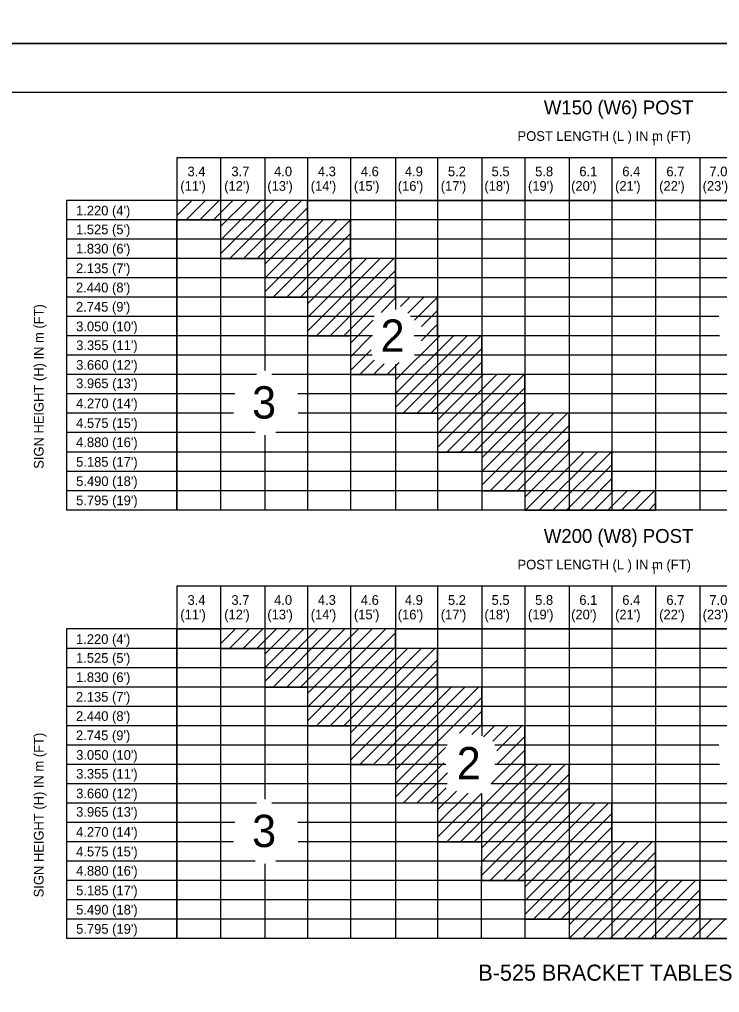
# Model space of a CAD drawing. Extents: x 637580 to 641008, y 294594 to 295782.
# Drawn here: x 639497.1 to 639714, y 294893.4 to 295195.1 of the extents above; entities that cross this region are included whole.
import ezdxf

# ---------------------------------------------------------------- set-up
doc = ezdxf.new("R2010")
doc.units = 0
for name, color, linetype in [('1', 7, 'Continuous'), ('2', 7, 'Continuous'), ('PLT-BNDY', 7, 'Continuous')]:
    doc.layers.add(name, color=color, linetype=linetype)

msp = doc.modelspace()

# ---------------------------------------------------------------- linework, layer by layer
at = {"layer": '1'}
msp.add_line((639302.31, 295172.63), (640088.31, 295172.63), dxfattribs=at)
at = {"layer": '2'}
for p, q in [((639866.29, 295152.27), (639545.88, 295152.27)), ((639545.88, 295152.27), (639545.88, 295043.01)), ((639559.39, 295152.27), (639559.39, 295043.01)), ((639573.15, 295152.27), (639573.15, 295086.26)), ((639586.4, 295152.27), (639586.4, 295043.01)), ((639599.66, 295152.27), (639599.66, 295043.01)), ((639613.67, 295152.27), (639613.67, 295105.22)), ((639626.67, 295152.27), (639626.67, 295043.01)), ((639640.43, 295152.27), (639640.43, 295043.01)), ((639653.69, 295152.27), (639653.69, 295043.01)), ((639667.45, 295152.27), (639667.45, 295043.01)), ((639680.7, 295152.27), (639680.7, 295043.01)), ((639694.21, 295152.27), (639694.21, 295043.01)), ((639707.97, 295152.27), (639707.97, 295043.01)), ((639866.29, 295139.01), (639511.65, 295139.01)), ((639511.65, 295139.01), (639511.65, 295043.01)), ((639545.88, 295139.01), (639545.88, 295133.01)), ((639551.38, 295139.01), (639545.88, 295139.01)), ((639545.88, 295138.6), (639546.29, 295139.01)), ((639545.88, 295134.36), (639550.53, 295139.01)), ((639548.78, 295133.01), (639554.78, 295139.01)), ((639586.4, 295139.01), (639551.38, 295139.01)), ((639553.02, 295133.01), (639559.02, 295139.01)), ((639557.26, 295133.01), (639563.26, 295139.01)), ((639559.39, 295130.9), (639567.5, 295139.01)), ((639559.39, 295126.65), (639571.75, 295139.01)), ((639559.39, 295122.41), (639575.99, 295139.01)), ((639562.23, 295121.01), (639580.23, 295139.01)), ((639566.47, 295121.01), (639584.47, 295139.01)), ((639586.4, 295133.01), (639586.4, 295139.01)), ((639586.4, 295139.01), (639827.27, 295139.01)), ((639570.72, 295121.01), (639586.4, 295136.7)), ((639827.27, 295133.01), (639511.65, 295133.01)), ((639545.88, 295043.01), (639545.88, 295133.01)), ((639545.88, 295133.01), (639559.39, 295133.01)), ((639545.88, 295133.01), (639559.39, 295133.01)), ((639559.39, 295133.01), (639559.39, 295121.01)), ((639559.39, 295133.01), (639559.39, 295121.01)), ((639573.15, 295119.2), (639586.96, 295133.01)), ((639573.15, 295114.95), (639591.2, 295133.01)), ((639573.15, 295110.71), (639595.44, 295133.01)), ((639575.69, 295109.01), (639599.66, 295132.98)), ((639599.66, 295133.01), (639586.4, 295133.01)), ((639599.66, 295121.01), (639599.66, 295133.01)), ((639840.28, 295127.01), (639511.65, 295127.01)), ((639579.93, 295109.01), (639599.66, 295128.74)), ((639584.17, 295109.01), (639599.66, 295124.5)), ((639840.28, 295121.01), (639511.65, 295121.01)), ((639559.39, 295121.01), (639573.15, 295121.01)), ((639559.39, 295121.01), (639573.15, 295121.01)), ((639573.15, 295121.01), (639573.15, 295109.01)), ((639573.15, 295121.01), (639573.15, 295109.01)), ((639586.4, 295107), (639600.41, 295121.01)), ((639586.4, 295102.75), (639604.66, 295121.01)), ((639586.4, 295098.51), (639608.9, 295121.01)), ((639589.14, 295097.01), (639613.14, 295121.01)), ((639613.67, 295121.01), (639599.66, 295121.01)), ((639613.67, 295109.01), (639613.67, 295121.01)), ((639593.39, 295097.01), (639613.67, 295117.29)), ((639853.28, 295115.01), (639511.65, 295115.01)), ((639597.63, 295097.01), (639613.67, 295113.05)), ((639853.28, 295109.01), (639511.65, 295109.01)), ((639573.15, 295109.01), (639586.4, 295109.01)), ((639573.15, 295109.01), (639586.4, 295109.01)), ((639586.4, 295109.01), (639586.4, 295097.01)), ((639586.4, 295109.01), (639586.4, 295097.01)), ((639609.14, 295104.28), (639613.87, 295109.01)), ((639626.67, 295109.01), (639613.67, 295109.01)), ((639615.2, 295106.09), (639618.11, 295109.01)), ((639617.45, 295104.1), (639622.36, 295109.01)), ((639619.51, 295101.92), (639626.6, 295109.01)), ((639626.67, 295097.01), (639626.67, 295109.01)), ((639607.01, 295103.01), (639511.65, 295103.01)), ((639713.86, 295103.01), (639618.23, 295103.01)), ((639621.73, 295099.9), (639626.67, 295104.84)), ((639599.66, 295094.8), (639606.72, 295101.86)), ((639621.58, 295095.51), (639626.67, 295100.6)), ((639606.46, 295097.01), (639511.65, 295097.01)), ((639586.4, 295097.01), (639599.66, 295097.01)), ((639586.4, 295097.01), (639599.66, 295097.01)), ((639599.66, 295097.01), (639599.66, 295085.01)), ((639599.66, 295097.01), (639599.66, 295085.01)), ((639599.66, 295090.56), (639606.11, 295097.01)), ((639613.67, 295083.35), (639627.33, 295097.01)), ((639613.67, 295079.11), (639631.57, 295097.01)), ((639613.67, 295074.86), (639635.81, 295097.01)), ((639616.05, 295073.01), (639640.05, 295097.01)), ((639714.04, 295097.01), (639619.44, 295097.01)), ((639640.43, 295097.01), (639626.67, 295097.01)), ((639640.43, 295085.01), (639640.43, 295097.01)), ((639620.3, 295073.01), (639640.43, 295093.14)), ((639606.35, 295091.01), (639511.65, 295091.01)), ((639599.66, 295086.31), (639606.09, 295092.74)), ((639866.29, 295091.01), (639619.55, 295091.01)), ((639602.6, 295085.01), (639607.03, 295089.44)), ((639606.84, 295085.01), (639610.13, 295088.3)), ((639611.08, 295085.01), (639614.79, 295088.71)), ((639613.67, 295088.28), (639613.67, 295043.01)), ((639624.54, 295073.01), (639640.43, 295088.9)), ((639570.59, 295085.01), (639511.65, 295085.01)), ((639866.29, 295085.01), (639575.26, 295085.01)), ((639599.66, 295085.01), (639613.67, 295085.01)), ((639599.66, 295085.01), (639613.67, 295085.01)), ((639613.67, 295085.01), (639613.67, 295073.01)), ((639613.67, 295085.01), (639613.67, 295073.01)), ((639626.67, 295070.9), (639640.78, 295085.01)), ((639626.67, 295066.66), (639645.02, 295085.01)), ((639626.67, 295062.42), (639649.27, 295085.01)), ((639629.51, 295061.01), (639653.51, 295085.01)), ((639653.69, 295085.01), (639640.43, 295085.01)), ((639653.69, 295073.01), (639653.69, 295085.01)), ((639633.75, 295061.01), (639653.69, 295080.94)), ((639563.85, 295079.01), (639511.65, 295079.01)), ((639866.29, 295079.01), (639583.36, 295079.01)), ((639638, 295061.01), (639653.69, 295076.7)), ((639563.44, 295073.01), (639511.65, 295073.01)), ((639866.29, 295073.01), (639583.5, 295073.01)), ((639613.67, 295073.01), (639626.67, 295073.01)), ((639613.67, 295073.01), (639626.67, 295073.01)), ((639626.67, 295073.01), (639626.67, 295061.01)), ((639626.67, 295073.01), (639626.67, 295061.01)), ((639640.43, 295059.2), (639654.24, 295073.01)), ((639640.43, 295054.96), (639658.48, 295073.01)), ((639640.43, 295050.72), (639662.72, 295073.01)), ((639642.97, 295049.01), (639666.97, 295073.01)), ((639667.45, 295073.01), (639653.69, 295073.01)), ((639667.45, 295061.01), (639667.45, 295073.01)), ((639647.21, 295049.01), (639667.45, 295069.25)), ((639570.17, 295067.01), (639511.65, 295067.01)), ((639573.15, 295066.19), (639573.15, 295043.01)), ((639866.29, 295067.01), (639576.49, 295067.01)), ((639651.45, 295049.01), (639667.45, 295065)), ((639866.29, 295061.01), (639511.65, 295061.01)), ((639626.67, 295061.01), (639640.43, 295061.01)), ((639626.67, 295061.01), (639640.43, 295061.01)), ((639640.43, 295061.01), (639640.43, 295049.01)), ((639640.43, 295061.01), (639640.43, 295049.01)), ((639653.69, 295047), (639667.69, 295061.01)), ((639653.94, 295043.01), (639671.94, 295061.01)), ((639658.18, 295043.01), (639676.18, 295061.01)), ((639662.42, 295043.01), (639680.42, 295061.01)), ((639680.7, 295061.01), (639667.45, 295061.01)), ((639680.7, 295049.01), (639680.7, 295061.01)), ((639666.66, 295043.01), (639680.7, 295057.05)), ((639866.29, 295055.01), (639511.65, 295055.01)), ((639670.91, 295043.01), (639680.7, 295052.8)), ((639866.29, 295049.01), (639511.65, 295049.01)), ((639640.43, 295049.01), (639653.69, 295049.01)), ((639640.43, 295049.01), (639653.69, 295049.01)), ((639653.69, 295049.01), (639653.69, 295043.01)), ((639653.69, 295049.01), (639653.69, 295043.01)), ((639675.15, 295043.01), (639681.15, 295049.01)), ((639679.39, 295043.01), (639685.39, 295049.01)), ((639694.21, 295049.01), (639680.7, 295049.01)), ((639683.64, 295043.01), (639689.64, 295049.01)), ((639687.88, 295043.01), (639693.88, 295049.01)), ((639694.21, 295043.01), (639694.21, 295049.01)), ((639692.12, 295043.01), (639694.21, 295045.1)), ((639866.29, 295043.01), (639511.65, 295043.01)), ((639653.69, 295043.01), (639545.88, 295043.01)), ((639653.69, 295043.01), (639694.21, 295043.01)), ((639866.29, 295043.01), (639694.21, 295043.01)), ((639866.29, 295019.39), (639545.88, 295019.39)), ((639545.88, 295019.39), (639545.88, 294910.13)), ((639559.39, 295019.39), (639559.39, 294910.13)), ((639573.15, 295019.39), (639573.15, 294953.39)), ((639586.4, 295019.39), (639586.4, 294910.13)), ((639599.66, 295019.39), (639599.66, 294910.13)), ((639613.67, 295019.39), (639613.67, 294910.13)), ((639626.67, 295019.39), (639626.67, 294910.13)), ((639640.43, 295019.39), (639640.33, 294973.02)), ((639653.69, 295019.39), (639653.69, 294910.13)), ((639667.45, 295019.39), (639667.45, 294910.13)), ((639680.7, 295019.39), (639680.7, 294910.13)), ((639694.21, 295019.39), (639694.21, 294910.13)), ((639707.97, 295019.39), (639707.97, 294910.13)), ((639866.29, 295006.13), (639511.65, 295006.13)), ((639511.65, 295006.13), (639511.65, 294910.13)), ((639545.88, 294910.13), (639545.88, 295006.13)), ((639545.88, 295006.13), (639559.39, 295006.13)), ((639559.4, 295006.13), (639559.4, 295000.11)), ((639564.96, 295006.13), (639559.4, 295006.13)), ((639559.4, 295005.79), (639559.74, 295006.13)), ((639559.4, 295001.55), (639563.99, 295006.13)), ((639562.21, 295000.11), (639568.23, 295006.13)), ((639613.67, 295006.13), (639564.96, 295006.13)), ((639566.45, 295000.11), (639572.47, 295006.13)), ((639570.69, 295000.11), (639576.72, 295006.13)), ((639573.13, 294998.31), (639580.96, 295006.13)), ((639573.13, 294994.07), (639585.2, 295006.13)), ((639573.13, 294989.82), (639589.44, 295006.13)), ((639575.69, 294988.14), (639593.69, 295006.13)), ((639579.94, 294988.14), (639597.93, 295006.13)), ((639584.18, 294988.14), (639602.17, 295006.13)), ((639586.4, 294986.12), (639606.41, 295006.13)), ((639586.4, 294981.88), (639610.66, 295006.13)), ((639613.66, 295000.13), (639613.67, 295006.13)), ((639613.67, 295006.13), (639827.27, 295006.13)), ((639586.4, 294977.63), (639613.66, 295004.9)), ((639827.27, 295000.13), (639511.65, 295000.13)), ((639559.4, 295000.11), (639573.13, 295000.11)), ((639573.13, 295000.11), (639573.13, 294988.14)), ((639589.14, 294976.13), (639613.64, 295000.63)), ((639593.38, 294976.13), (639617.31, 295000.06)), ((639597.63, 294976.13), (639621.55, 295000.06)), ((639599.68, 294973.94), (639625.79, 295000.05)), ((639626.64, 295000.13), (639613.66, 295000.13)), ((639626.67, 294988.14), (639626.64, 295000.13)), ((639599.68, 294969.7), (639626.7, 294996.72)), ((639840.28, 294994.13), (639511.65, 294994.13)), ((639599.68, 294965.45), (639626.68, 294992.46)), ((639840.28, 294988.13), (639511.65, 294988.13)), ((639573.13, 294988.14), (639586.4, 294988.14)), ((639586.4, 294988.14), (639586.4, 294976.13)), ((639602.57, 294964.11), (639626.67, 294988.2)), ((639606.82, 294964.11), (639630.85, 294988.14)), ((639611.06, 294964.11), (639635.09, 294988.14)), ((639613.66, 294962.46), (639639.34, 294988.14)), ((639640.36, 294988.15), (639626.67, 294988.14)), ((639640.36, 294976.13), (639640.36, 294988.15)), ((639613.66, 294958.22), (639640.36, 294984.93)), ((639853.28, 294982.13), (639511.65, 294982.13)), ((639633.46, 294973.79), (639640.36, 294980.68)), ((639853.28, 294976.13), (639511.65, 294976.13)), ((639586.4, 294976.13), (639599.68, 294976.13)), ((639599.68, 294976.13), (639599.68, 294964.11)), ((639637.33, 294973.41), (639640.36, 294976.44)), ((639653.68, 294976.13), (639640.36, 294976.13)), ((639640.89, 294972.73), (639644.32, 294976.15)), ((639643.75, 294971.34), (639648.56, 294976.15)), ((639645.05, 294968.4), (639652.8, 294976.15)), ((639653.68, 294964.11), (639653.68, 294976.13)), ((639645.02, 294964.13), (639653.7, 294972.81)), ((639613.67, 294970.13), (639511.65, 294970.13)), ((639613.66, 294953.98), (639629.09, 294969.41)), ((639629.63, 294970.13), (639613.67, 294970.13)), ((639713.86, 294970.13), (639644.42, 294970.13)), ((639643.27, 294958.13), (639653.7, 294968.56)), ((639606.46, 294964.13), (639511.65, 294964.13)), ((639599.68, 294964.11), (639613.66, 294964.11)), ((639613.66, 294964.11), (639613.66, 294952.18)), ((639629.25, 294964.13), (639613.67, 294964.13)), ((639616.1, 294952.18), (639628.59, 294964.67)), ((639629.52, 294940.14), (639653.7, 294964.32)), ((639633.76, 294940.14), (639657.71, 294964.09)), ((639638.01, 294940.14), (639661.95, 294964.09)), ((639640.28, 294938.17), (639666.2, 294964.09)), ((639714.04, 294964.13), (639644.42, 294964.13)), ((639667.45, 294964.11), (639653.68, 294964.11)), ((639667.46, 294952.11), (639667.45, 294964.11)), ((639620.34, 294952.18), (639629.7, 294961.53)), ((639640.28, 294933.93), (639667.46, 294961.11)), ((639613.67, 294958.13), (639511.65, 294958.13)), ((639629.6, 294958.13), (639613.67, 294958.13)), ((639866.29, 294958.13), (639643.27, 294958.13)), ((639624.58, 294952.18), (639629.28, 294956.87)), ((639626.69, 294950.04), (639632.53, 294955.88)), ((639626.69, 294945.8), (639636.15, 294955.26)), ((639626.69, 294941.55), (639640.29, 294955.16)), ((639640.29, 294955.16), (639640.19, 294910.13)), ((639640.28, 294929.69), (639667.46, 294956.87)), ((639570.59, 294952.13), (639511.65, 294952.13)), ((639866.29, 294952.13), (639575.26, 294952.13)), ((639613.66, 294952.18), (639626.69, 294952.18)), ((639626.69, 294952.18), (639626.69, 294940.14)), ((639642.97, 294928.13), (639667.46, 294952.63)), ((639647.21, 294928.13), (639671.19, 294952.11)), ((639651.45, 294928.13), (639675.43, 294952.11)), ((639653.69, 294926.13), (639679.67, 294952.11)), ((639680.71, 294952.11), (639667.46, 294952.11)), ((639680.71, 294940.15), (639680.71, 294952.11)), ((639653.69, 294921.88), (639680.71, 294948.91)), ((639563.85, 294946.13), (639511.65, 294946.13)), ((639866.29, 294946.13), (639583.36, 294946.13)), ((639653.69, 294917.64), (639680.71, 294944.67)), ((639563.44, 294940.13), (639511.65, 294940.13)), ((639866.29, 294940.13), (639583.5, 294940.13)), ((639626.69, 294940.14), (639640.28, 294940.14)), ((639640.28, 294940.14), (639640.28, 294928.13)), ((639656.44, 294916.15), (639680.71, 294940.42)), ((639660.68, 294916.15), (639684.68, 294940.15)), ((639664.92, 294916.15), (639688.93, 294940.15)), ((639667.45, 294914.43), (639693.17, 294940.16)), ((639694.21, 294940.13), (639680.71, 294940.15)), ((639694.22, 294928.14), (639694.21, 294940.13)), ((639667.45, 294910.19), (639694.24, 294936.98)), ((639570.17, 294934.13), (639511.65, 294934.13)), ((639573.15, 294933.32), (639573.15, 294910.13)), ((639866.29, 294934.13), (639576.49, 294934.13)), ((639671.63, 294910.13), (639694.25, 294932.75)), ((639866.29, 294928.13), (639511.65, 294928.13)), ((639640.28, 294928.13), (639653.69, 294928.13)), ((639653.69, 294928.13), (639653.69, 294916.15)), ((639675.88, 294910.13), (639694.21, 294928.47)), ((639680.12, 294910.13), (639698.11, 294928.13)), ((639684.36, 294910.13), (639702.35, 294928.12)), ((639688.6, 294910.13), (639706.58, 294928.11)), ((639694.29, 294928.13), (639694.22, 294928.14)), ((639707.96, 294928.14), (639694.29, 294928.13)), ((639707.97, 294916.13), (639707.96, 294928.14)), ((639692.84, 294910.13), (639707.95, 294925.24)), ((639866.29, 294922.13), (639511.65, 294922.13)), ((639697.09, 294910.13), (639707.93, 294920.98)), ((639866.29, 294916.13), (639511.65, 294916.13)), ((639653.69, 294916.15), (639667.45, 294916.15)), ((639667.45, 294916.15), (639667.45, 294910.13)), ((639701.33, 294910.13), (639707.97, 294916.77)), ((639705.57, 294910.13), (639711.6, 294916.15)), ((639709.81, 294910.13), (639715.84, 294916.15)), ((639866.29, 294910.13), (639511.65, 294910.13)), ((639667.45, 294910.13), (639545.88, 294910.13)), ((639667.45, 294910.13), (639721.72, 294910.13))]:
    msp.add_line(p, q, dxfattribs=at)
msp.add_lwpolyline([(639721.72, 294910.13), (639721.72, 294910.18), (639721.72, 294916.14), (639707.97, 294916.13)], dxfattribs=at)
at = {"layer": 'PLT-BNDY'}
for points in [[(639262.31, 295781.63), (640103.31, 295781.63), (640103.31, 295187.63), (639262.31, 295187.63)], [(639262.31, 295187.63), (640103.31, 295187.63), (640103.31, 294593.63), (639262.31, 294593.63)]]:
    msp.add_lwpolyline(points, close=True, dxfattribs=at)

# ---------------------------------------------------------------- texts
at = {"layer": '2'}
for s, height, p in [('W150 (W6) POST', 4.3, (639659.6, 295165.7)), ('POST LENGTH (L ) IN m (FT)', 3, (639651.45, 295157.48)), ('T', 2, (639692.99, 295156.09)), ('3.4', 3, (639549.16, 295146.5)), ('3.7', 3, (639562.76, 295146.5)), ('4.0', 3, (639576, 295146.5)), ('4.3', 3, (639589.57, 295146.5)), ('4.6', 3, (639602.88, 295146.5)), ('4.9', 3, (639616.53, 295146.5)), ('5.2', 3, (639629.88, 295146.5)), ('5.5', 3, (639643.4, 295146.5)), ('5.8', 3, (639656.9, 295146.5)), ('6.1', 3, (639670.6, 295146.5)), ('6.4', 3, (639683.9, 295146.5)), ('6.7', 3, (639697.57, 295146.5)), ('7.0', 3, (639710.91, 295146.5)), ("(11')", 3, (639546.93, 295142)), ("(12')", 3, (639560.53, 295142)), ("(13')", 3, (639573.89, 295142)), ("(14')", 3, (639587.34, 295142)), ("(15')", 3, (639600.73, 295142)), ("(16')", 3, (639614.32, 295142)), ("(17')", 3, (639627.65, 295142)), ("(18')", 3, (639641.17, 295142)), ("(19')", 3, (639654.68, 295142)), ("(20')", 3, (639668.05, 295142)), ("(21')", 3, (639681.67, 295142)), ("(22')", 3, (639695.34, 295142)), ("(23')", 3, (639708.81, 295142)), ("1.220 (4')", 3, (639514.61, 295134.37)), ("1.525 (5')", 3, (639514.61, 295128.53)), ("1.830 (6')", 3, (639514.62, 295122.56)), ("2.135 (7')", 3, (639514.61, 295116.47)), ("2.440 (8')", 3, (639514.61, 295110.5)), ("2.745 (9')", 3, (639514.59, 295104.54)), ('2', 10, (639609, 295092.1)), ("3.050 (10')", 3, (639514.65, 295098.45)), ("3.355 (11')", 3, (639514.65, 295092.61)), ("3.660 (12')", 3, (639514.65, 295086.52)), ("3.965 (13')", 3, (639514.65, 295080.8)), ('3', 10, (639569.18, 295071.39)), ("4.270 (14')", 3, (639514.65, 295074.58)), ("4.575 (15')", 3, (639514.65, 295068.49)), ("4.880 (16')", 3, (639514.65, 295062.53)), ("5.185 (17')", 3, (639514.65, 295056.44)), ("5.490 (18')", 3, (639514.65, 295050.47)), ("5.795 (19')", 3, (639514.65, 295044.51)), ('W200 (W8) POST', 4.3, (639659.6, 295032.83)), ('POST LENGTH (L ) IN m (FT)', 3, (639651.45, 295024.6)), ('T', 2, (639692.99, 295023.22)), ('3.4', 3, (639549.16, 295013.62)), ('3.7', 3, (639562.76, 295013.62)), ('4.0', 3, (639576, 295013.62)), ('4.3', 3, (639589.57, 295013.62)), ('4.6', 3, (639602.88, 295013.62)), ('4.9', 3, (639616.53, 295013.62)), ('5.2', 3, (639629.88, 295013.62)), ('5.5', 3, (639643.4, 295013.62)), ('5.8', 3, (639656.9, 295013.62)), ('6.1', 3, (639670.6, 295013.62)), ('6.4', 3, (639683.9, 295013.62)), ('6.7', 3, (639697.57, 295013.62)), ('7.0', 3, (639710.91, 295013.62)), ("(11')", 3, (639546.93, 295009.12)), ("(12')", 3, (639560.53, 295009.12)), ("(13')", 3, (639573.89, 295009.12)), ("(14')", 3, (639587.34, 295009.12)), ("(15')", 3, (639600.73, 295009.12)), ("(16')", 3, (639614.32, 295009.12)), ("(17')", 3, (639627.65, 295009.12)), ("(18')", 3, (639641.17, 295009.12)), ("(19')", 3, (639654.68, 295009.12)), ("(20')", 3, (639668.05, 295009.12)), ("(21')", 3, (639681.67, 295009.12)), ("(22')", 3, (639695.34, 295009.12)), ("(23')", 3, (639708.81, 295009.12)), ("1.220 (4')", 3, (639514.61, 295001.5)), ("1.525 (5')", 3, (639514.61, 294995.65)), ("1.830 (6')", 3, (639514.62, 294989.68)), ("2.135 (7')", 3, (639514.61, 294983.59)), ("2.440 (8')", 3, (639514.61, 294977.63)), ("2.745 (9')", 3, (639514.59, 294971.66)), ('2', 10, (639632.59, 294959.54)), ("3.050 (10')", 3, (639514.65, 294965.57)), ("3.355 (11')", 3, (639514.65, 294959.73)), ("3.660 (12')", 3, (639514.65, 294953.64)), ("3.965 (13')", 3, (639514.65, 294947.93)), ('3', 10, (639569.18, 294938.52)), ("4.270 (14')", 3, (639514.65, 294941.71)), ("4.575 (15')", 3, (639514.65, 294935.62)), ("4.880 (16')", 3, (639514.65, 294929.65)), ("5.185 (17')", 3, (639514.65, 294923.56)), ("5.490 (18')", 3, (639514.65, 294917.6)), ("5.795 (19')", 3, (639514.65, 294911.63)), ('B-525 BRACKET TABLES', 5, (639639.3, 294897.07))]:
    msp.add_text(s, height=height, dxfattribs=at).set_placement(p)
for p in [(639504.56, 295055.81), (639504.56, 294922.93)]:
    msp.add_text('SIGN HEIGHT (H) IN m (FT)', height=3, rotation=90, dxfattribs=at).set_placement(p)

doc.saveas('drawing.dxf')
